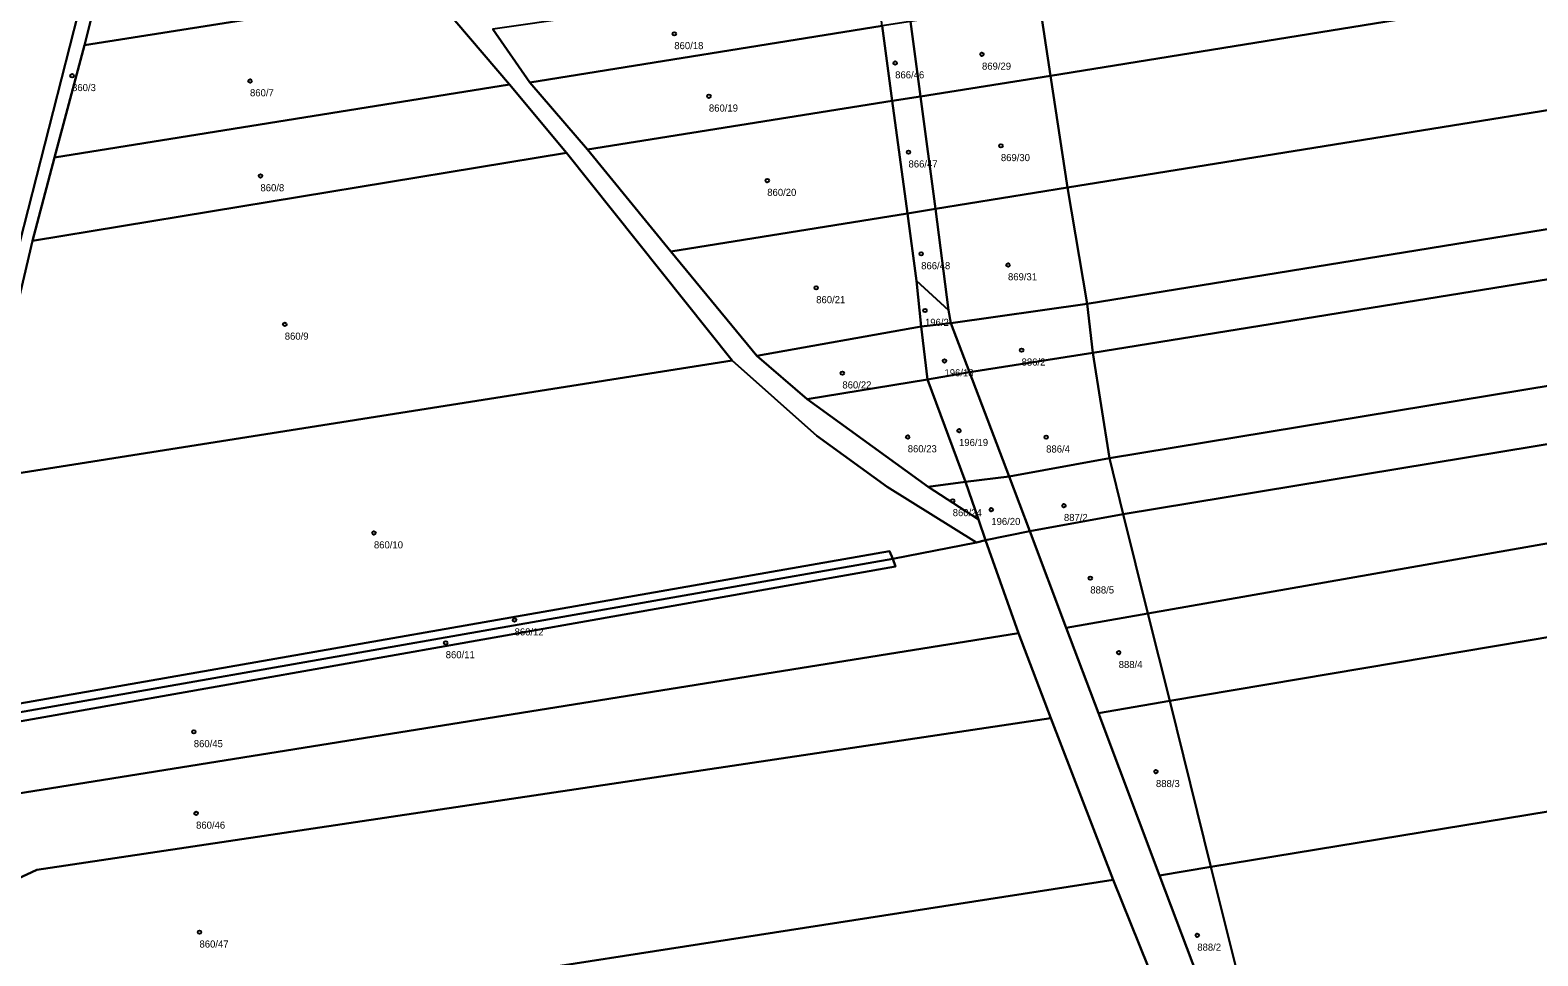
# Model space of a CAD drawing. Extents: x -587171 to -555306, y -1167727 to -1074732.
# Drawn here: x -584940 to -584727.9, y -1165569.5 to -1165439.3 of the extents above; entities that cross this region are included whole.
import ezdxf

# ---------------------------------------------------------------- set-up
doc = ezdxf.new("R2010")
doc.units = 0
doc.layers.add('Definiční body', color=7, linetype='Continuous')
doc.layers.add('Polygon parcely', color=7, linetype='Continuous')

msp = doc.modelspace()

# ---------------------------------------------------------------- linework, layer by layer
at = {"layer": 'Definiční body'}
for centre in [(-584849.38, -1165439.81), (-584818.3, -1165443.92), (-584806.08, -1165442.7), (-584934.13, -1165445.71), (-584909.09, -1165446.44), (-584844.51, -1165448.59), (-584816.42, -1165456.45), (-584803.42, -1165455.56), (-584907.62, -1165459.8), (-584836.3, -1165460.45), (-584814.64, -1165470.76), (-584802.42, -1165472.32), (-584829.41, -1165475.54), (-584904.2, -1165480.67), (-584814.1, -1165478.73), (-584800.51, -1165484.31), (-584811.36, -1165485.82), (-584825.73, -1165487.53), (-584816.53, -1165496.51), (-584809.31, -1165495.62), (-584797.05, -1165496.54), (-584810.2, -1165505.49), (-584794.55, -1165506.17), (-584804.77, -1165506.73), (-584891.65, -1165510.02), (-584790.84, -1165516.36), (-584871.86, -1165522.26), (-584881.55, -1165525.47), (-584786.84, -1165526.85), (-584917, -1165537.98), (-584781.6, -1165543.59), (-584916.68, -1165549.44), (-584916.2, -1165566.16), (-584775.78, -1165566.6)]:
    msp.add_circle(centre, 0.25, dxfattribs=at)
at = {"layer": 'Polygon parcely'}
for points in [[(-584225.63, -1165352.72), (-584234.7, -1165342.13), (-584382.81, -1165367.17), (-584556.85, -1165396.31), (-584677.37, -1165415.73), (-584798.03, -1165435.17), (-584796.43, -1165445.7), (-584675.02, -1165426.1), (-584553.98, -1165406.56), (-584379.31, -1165377.66)], [(-584214.53, -1165366.86), (-584221.82, -1165357.17), (-584225.63, -1165352.72), (-584379.31, -1165377.66), (-584553.98, -1165406.56), (-584675.02, -1165426.1), (-584796.43, -1165445.7), (-584794.03, -1165461.44), (-584670.52, -1165441.54), (-584547.57, -1165421.73), (-584380.19, -1165393.99)], [(-584207.62, -1165376.05), (-584214.53, -1165366.86), (-584380.19, -1165393.99), (-584547.57, -1165421.73), (-584670.52, -1165441.54), (-584794.03, -1165461.44), (-584791.3, -1165477.79), (-584675.08, -1165458.95), (-584558.98, -1165440.13), (-584555.53, -1165439.46), (-584455.48, -1165422.42), (-584353.66, -1165405.09), (-584203.76, -1165381.17)], [(-584953.66, -1165379.16), (-584971.92, -1165368.54), (-585005.85, -1165517.15), (-585002.31, -1165515.83), (-584997.11, -1165513.9), (-584991.97, -1165511.88), (-584986.52, -1165509.33), (-584981.47, -1165507.66), (-584976.27, -1165505.29), (-584971.31, -1165503.17), (-584966.14, -1165501.04), (-584961.72, -1165499.08), (-584956.22, -1165496.67), (-584951.29, -1165494.26), (-584947.38, -1165492.07), (-584923.91, -1165400.16)], [(-584936.62, -1165457.2), (-584932.39, -1165441.39), (-584929.45, -1165429.65), (-584926.85, -1165417.59), (-584922.77, -1165400.81), (-584923.91, -1165400.16), (-584947.38, -1165492.07), (-584944.94, -1165491.18), (-584939.72, -1165468.93)], [(-584883.83, -1165433.73), (-584893.28, -1165424.44), (-584929.45, -1165429.65), (-584932.39, -1165441.39)], [(-584883.83, -1165433.73), (-584932.39, -1165441.39), (-584936.62, -1165457.2), (-584872.59, -1165446.93)], [(-584869.72, -1165446.64), (-584820.11, -1165438.7), (-584820.6, -1165435.03), (-584826.19, -1165432.12), (-584874.94, -1165439.14)], [(-584796.43, -1165445.7), (-584798.03, -1165435.17), (-584816.16, -1165438.07), (-584814.75, -1165448.62)], [(-584814.75, -1165448.62), (-584816.16, -1165438.07), (-584820.11, -1165438.7), (-584818.7, -1165449.25)], [(-584818.7, -1165449.25), (-584820.11, -1165438.7), (-584869.72, -1165446.64), (-584861.58, -1165456.09)], [(-584558.98, -1165440.13), (-584675.08, -1165458.95), (-584791.3, -1165477.79), (-584790.47, -1165484.69), (-584674.41, -1165465.92), (-584557.93, -1165447.09)], [(-584552.07, -1165460.61), (-584555.53, -1165439.46), (-584558.98, -1165440.13), (-584557.93, -1165447.09), (-584674.41, -1165465.92), (-584790.47, -1165484.69), (-584788.15, -1165499.5), (-584671.82, -1165480.34), (-584555.72, -1165461.21)], [(-584794.03, -1165461.44), (-584796.43, -1165445.7), (-584814.75, -1165448.62), (-584812.63, -1165464.44)], [(-584864.54, -1165456.57), (-584872.59, -1165446.93), (-584936.62, -1165457.2), (-584939.72, -1165468.93)], [(-584812.63, -1165464.44), (-584814.75, -1165448.62), (-584818.7, -1165449.25), (-584816.58, -1165465.08)], [(-584816.58, -1165465.08), (-584818.7, -1165449.25), (-584861.58, -1165456.09), (-584849.85, -1165470.43)], [(-584864.54, -1165456.57), (-584939.72, -1165468.93), (-584944.94, -1165491.18), (-584947.3, -1165502.5), (-584841.25, -1165485.74)], [(-584786.21, -1165507.35), (-584670.52, -1165488.27), (-584554.39, -1165469.12), (-584555.72, -1165461.21), (-584671.82, -1165480.34), (-584788.15, -1165499.5)], [(-584791.3, -1165477.79), (-584794.03, -1165461.44), (-584812.63, -1165464.44), (-584810.8, -1165478.7), (-584810.48, -1165480.49)], [(-584814.66, -1165480.99), (-584815.32, -1165474.53), (-584816.58, -1165465.08), (-584849.85, -1165470.43), (-584837.79, -1165485.1)], [(-584812.63, -1165464.44), (-584816.58, -1165465.08), (-584815.32, -1165474.53), (-584810.8, -1165478.7)], [(-584782.74, -1165521.32), (-584618.11, -1165492.48), (-584548.1, -1165480.98), (-584550.87, -1165468.54), (-584554.39, -1165469.12), (-584670.52, -1165488.27), (-584786.21, -1165507.35)], [(-584815.32, -1165474.53), (-584814.66, -1165480.99), (-584810.48, -1165480.49), (-584810.8, -1165478.7)], [(-584807.85, -1165487.4), (-584790.47, -1165484.69), (-584791.3, -1165477.79), (-584810.48, -1165480.49)], [(-584813.75, -1165488.45), (-584807.85, -1165487.4), (-584810.48, -1165480.49), (-584814.66, -1165480.99)], [(-584830.67, -1165491.18), (-584813.75, -1165488.45), (-584814.66, -1165480.99), (-584837.79, -1165485.1)], [(-584625.02, -1165507.58), (-584545.06, -1165494.64), (-584548.1, -1165480.98), (-584618.11, -1165492.48), (-584782.74, -1165521.32), (-584779.67, -1165533.64)], [(-584790.47, -1165484.69), (-584807.85, -1165487.4), (-584802.28, -1165502.05), (-584788.15, -1165499.5)], [(-584829.32, -1165496.35), (-584841.25, -1165485.74), (-584947.3, -1165502.5), (-584944.94, -1165491.18), (-584947.38, -1165492.07), (-584951.29, -1165494.26), (-584960.66, -1165535.08), (-584952.51, -1165535.91), (-584819.11, -1165512.56), (-584818.63, -1165513.66), (-584806.85, -1165511.33), (-584819.43, -1165503.51)], [(-584830.67, -1165491.18), (-584813.65, -1165503.51), (-584808.42, -1165502.84), (-584813.75, -1165488.45)], [(-584808.42, -1165502.84), (-584802.28, -1165502.05), (-584807.85, -1165487.4), (-584813.75, -1165488.45)], [(-584616.29, -1165531.13), (-584539.66, -1165518.9), (-584545.06, -1165494.64), (-584625.02, -1165507.58), (-584779.67, -1165533.64), (-584773.86, -1165556.98)], [(-584799.33, -1165509.77), (-584786.21, -1165507.35), (-584788.15, -1165499.5), (-584802.28, -1165502.05)], [(-584806.57, -1165508.13), (-584808.42, -1165502.84), (-584813.65, -1165503.51)], [(-584805.61, -1165511), (-584799.33, -1165509.77), (-584802.28, -1165502.05), (-584808.42, -1165502.84), (-584806.57, -1165508.13)], [(-584786.21, -1165507.35), (-584799.33, -1165509.77), (-584794.22, -1165523.33), (-584782.74, -1165521.32)], [(-584952.51, -1165535.91), (-584952.14, -1165537.08), (-584818.63, -1165513.66), (-584819.11, -1165512.56)], [(-584951.94, -1165538.34), (-584818.23, -1165514.73), (-584818.63, -1165513.66), (-584952.14, -1165537.08)], [(-584767.75, -1165581.52), (-584603.23, -1165554.26), (-584533.99, -1165543.05), (-584535.41, -1165537.99), (-584539.66, -1165518.9), (-584616.29, -1165531.13), (-584773.86, -1165556.98)], [(-584794.22, -1165523.33), (-584789.7, -1165535.33), (-584779.67, -1165533.64), (-584782.74, -1165521.32)], [(-584796.39, -1165536.05), (-584800.92, -1165524.12), (-584948.17, -1165547.69), (-585039.17, -1165587.87), (-585039.37, -1165595.47), (-585036.23, -1165602.56), (-584939.08, -1165557.38)], [(-584773.86, -1165556.98), (-584779.67, -1165533.64), (-584789.7, -1165535.33), (-584781.1, -1165558.17)], [(-585015.4, -1165625.99), (-584930.01, -1165580.92), (-584787.64, -1165558.79), (-584796.39, -1165536.05), (-584939.08, -1165557.38), (-585036.23, -1165602.56), (-585024.6, -1165616.51), (-585016.64, -1165627.11)], [(-585004.46, -1165631.41), (-584988.92, -1165645.93), (-584919.65, -1165606.09), (-584778.32, -1165582.52), (-584780.23, -1165577.16), (-584787.64, -1165558.79), (-584930.01, -1165580.92), (-585015.4, -1165625.99)], [(-584781.1, -1165558.17), (-584774.87, -1165574.7), (-584771.62, -1165582.1), (-584767.75, -1165581.52), (-584773.86, -1165556.98)]]:
    msp.add_lwpolyline(points, close=True, dxfattribs=at)
for points in [[(-584883.83, -1165433.73), (-584872.59, -1165446.93), (-584864.54, -1165456.57), (-584841.25, -1165485.74), (-584829.32, -1165496.35), (-584819.43, -1165503.51), (-584806.85, -1165511.33), (-584805.61, -1165511), (-584806.57, -1165508.13), (-584813.65, -1165503.51), (-584830.67, -1165491.18), (-584837.79, -1165485.1), (-584849.85, -1165470.43), (-584861.58, -1165456.09), (-584869.72, -1165446.64), (-584874.94, -1165439.14)], [(-584774.87, -1165574.7), (-584781.1, -1165558.17), (-584789.7, -1165535.33), (-584794.22, -1165523.33), (-584799.33, -1165509.77), (-584805.61, -1165511), (-584800.92, -1165524.12), (-584796.39, -1165536.05), (-584787.64, -1165558.79), (-584780.23, -1165577.16)], [(-584948.17, -1165547.69), (-584800.92, -1165524.12), (-584805.61, -1165511), (-584806.85, -1165511.33), (-584818.63, -1165513.66), (-584818.23, -1165514.73), (-584951.94, -1165538.34)]]:
    msp.add_lwpolyline(points, dxfattribs=at)

# ---------------------------------------------------------------- texts
at = {"layer": 'Definiční body'}
for s, p in [('860/18', (-584849.38, -1165441.97)), ('869/29', (-584806.08, -1165444.86)), ('866/46', (-584818.3, -1165446.08)), ('860/3', (-584934.13, -1165447.87)), ('860/7', (-584909.09, -1165448.6)), ('860/19', (-584844.51, -1165450.75)), ('869/30', (-584803.42, -1165457.72)), ('866/47', (-584816.42, -1165458.61)), ('860/8', (-584907.62, -1165461.96)), ('860/20', (-584836.3, -1165462.61)), ('866/48', (-584814.64, -1165472.92)), ('869/31', (-584802.42, -1165474.48)), ('860/21', (-584829.41, -1165477.7)), ('196/2', (-584814.1, -1165480.89)), ('860/9', (-584904.2, -1165482.83)), ('886/2', (-584800.51, -1165486.47)), ('860/22', (-584825.73, -1165489.69)), ('196/18', (-584811.36, -1165487.98)), ('196/19', (-584809.31, -1165497.78)), ('860/23', (-584816.53, -1165498.67)), ('886/4', (-584797.05, -1165498.7)), ('860/24', (-584810.2, -1165507.65)), ('196/20', (-584804.77, -1165508.89)), ('887/2', (-584794.55, -1165508.33)), ('860/10', (-584891.65, -1165512.18)), ('888/5', (-584790.84, -1165518.52)), ('860/12', (-584871.86, -1165524.42)), ('860/11', (-584881.55, -1165527.63)), ('888/4', (-584786.84, -1165529.01)), ('860/45', (-584917, -1165540.14)), ('888/3', (-584781.6, -1165545.75)), ('860/46', (-584916.68, -1165551.6)), ('860/47', (-584916.2, -1165568.32)), ('888/2', (-584775.78, -1165568.76))]:
    msp.add_text(s, height=1, dxfattribs=at).set_placement(p)

doc.saveas('drawing.dxf')
